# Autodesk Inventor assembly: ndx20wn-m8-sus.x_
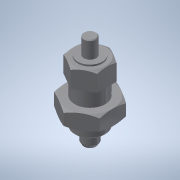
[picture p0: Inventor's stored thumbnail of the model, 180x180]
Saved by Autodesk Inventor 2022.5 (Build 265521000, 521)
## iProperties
Part Number: ndx20wn-m8-sus.x_
Material: 一般
Document SubType Name: Assembly
Designer: ImaoCorp
Sending System: SOLIDWORKS 2017-2017317
MC: AMD64
MC_MODEL: Intel64 Family 6 Model 60 Stepping 3, GenuineIntel
OS: Windows_NT
FRU: Parasolid Version 29.0, build 201,  4-17-2017
FORMAT: text
GUISE: transmit
KEY: ndx20wn-m8-sus
FILE: ndx20wn-m8-sus.x_t
DATE: Wed Sep 04 15:30:30 2019
Author: ImaoCorp
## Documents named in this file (3)
- X:\14_SW2022-Inv2022\00_全2023-1023新製品(TCC)まで\n\ndx20wn-m8-sus\NDX20WN-M8-SUS.iam
- X:\14_SW2022-Inv2022\00_全2023-1023新製品(TCC)まで\n\ndx20wn-m8-sus\ndx20wn-m8-sus_01.ipt
- X:\14_SW2022-Inv2022\00_全2023-1023新製品(TCC)まで\n\ndx20wn-m8-sus\ndx20wn-m8-sus_02.ipt
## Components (2 placed, 2 different names)
1. ndx20wn-m8-sus_01
2. ndx20wn-m8-sus_02
